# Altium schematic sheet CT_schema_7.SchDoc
size 522 x 483 mm
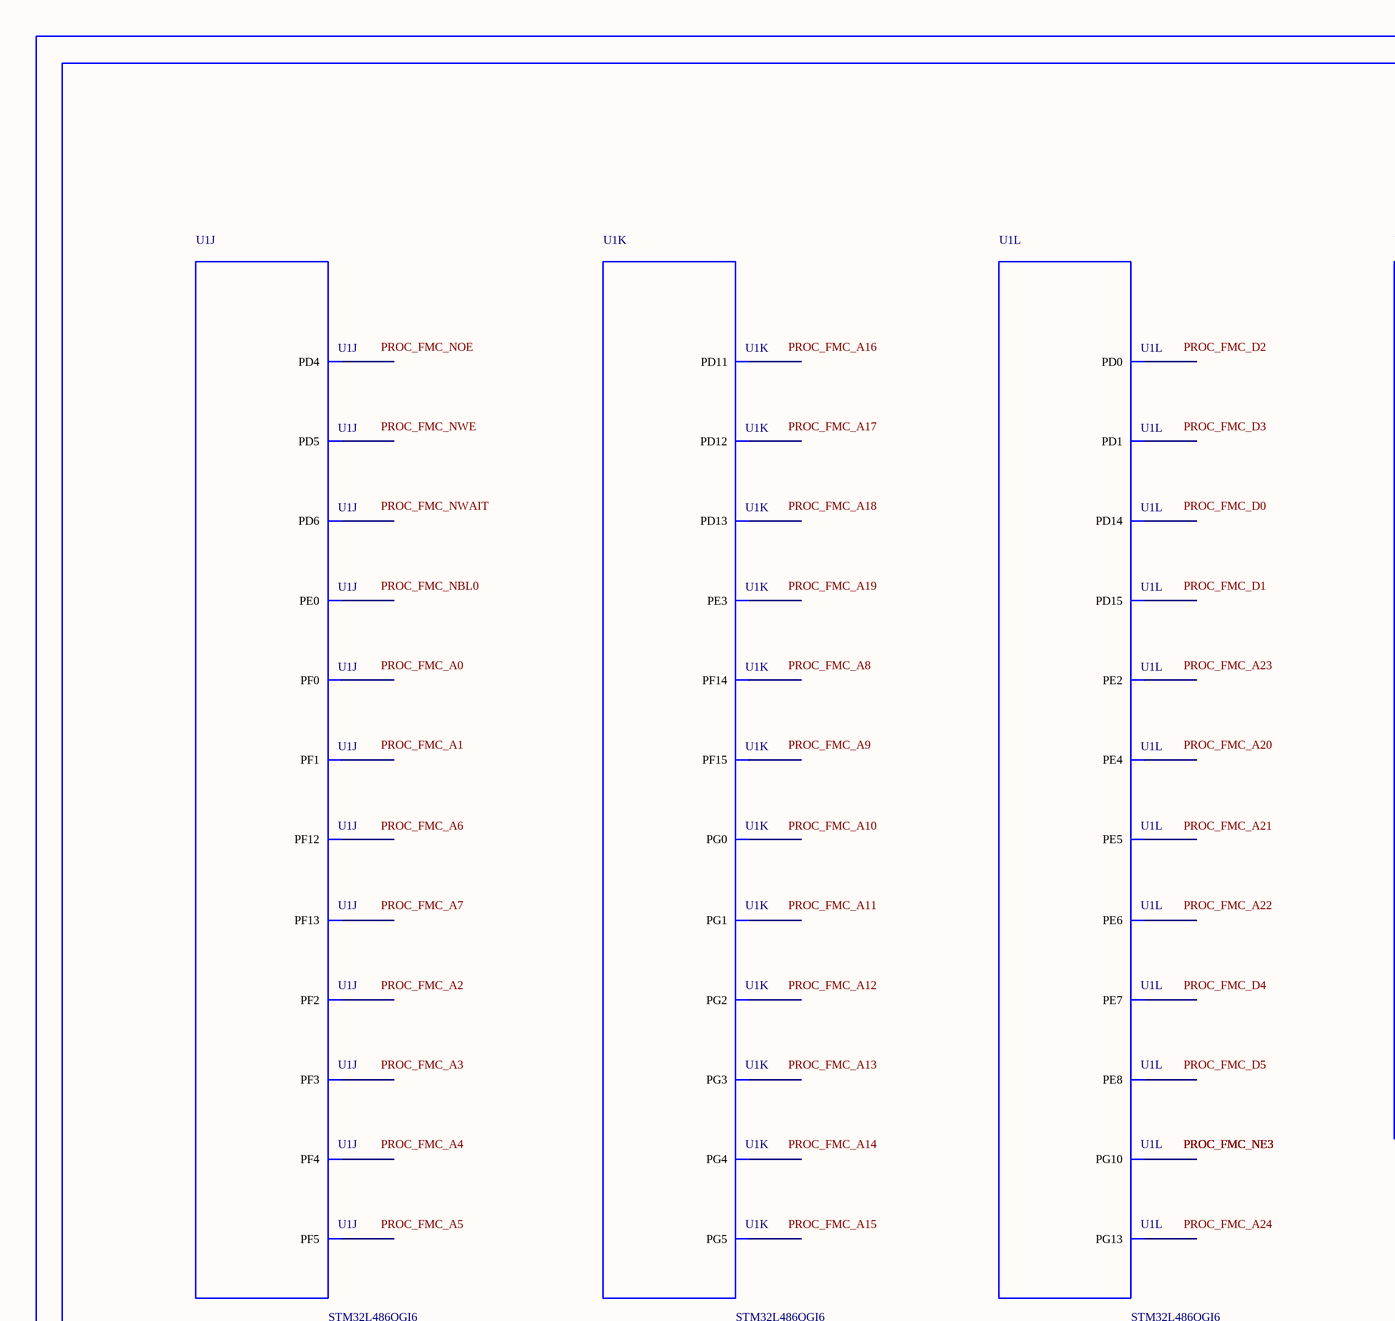
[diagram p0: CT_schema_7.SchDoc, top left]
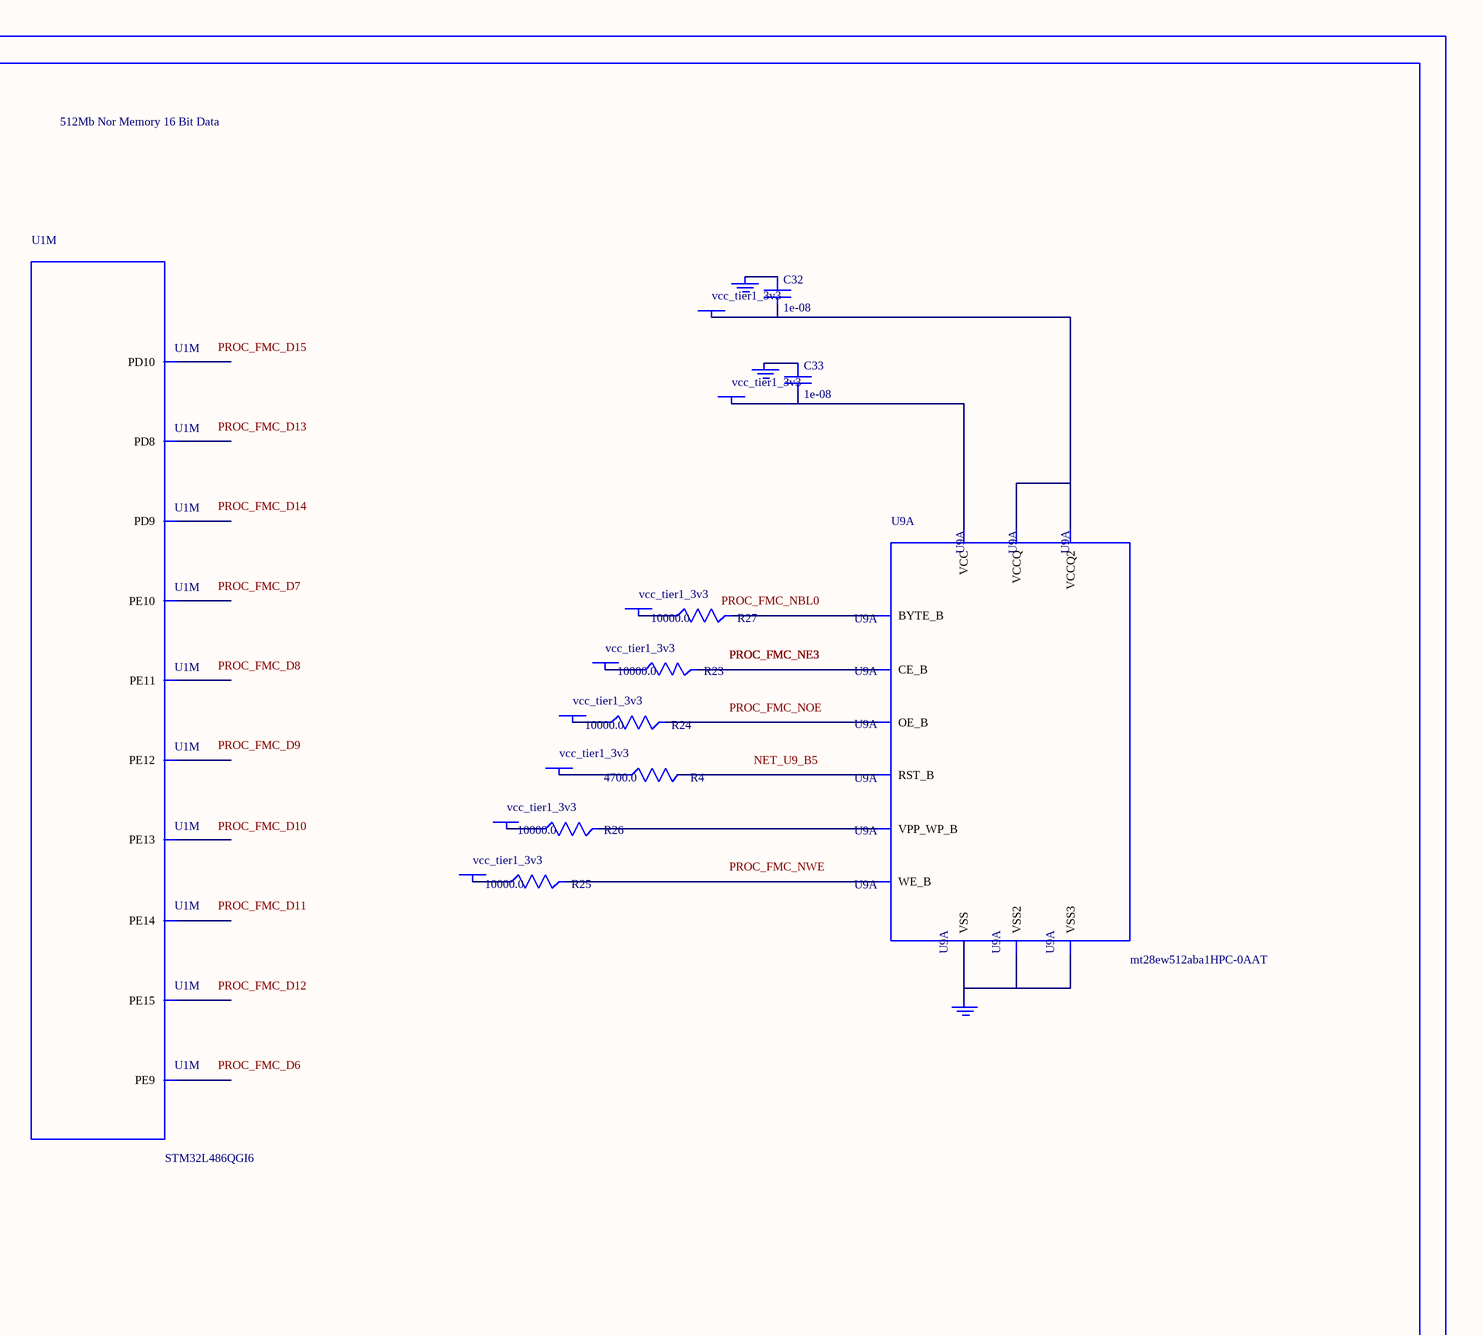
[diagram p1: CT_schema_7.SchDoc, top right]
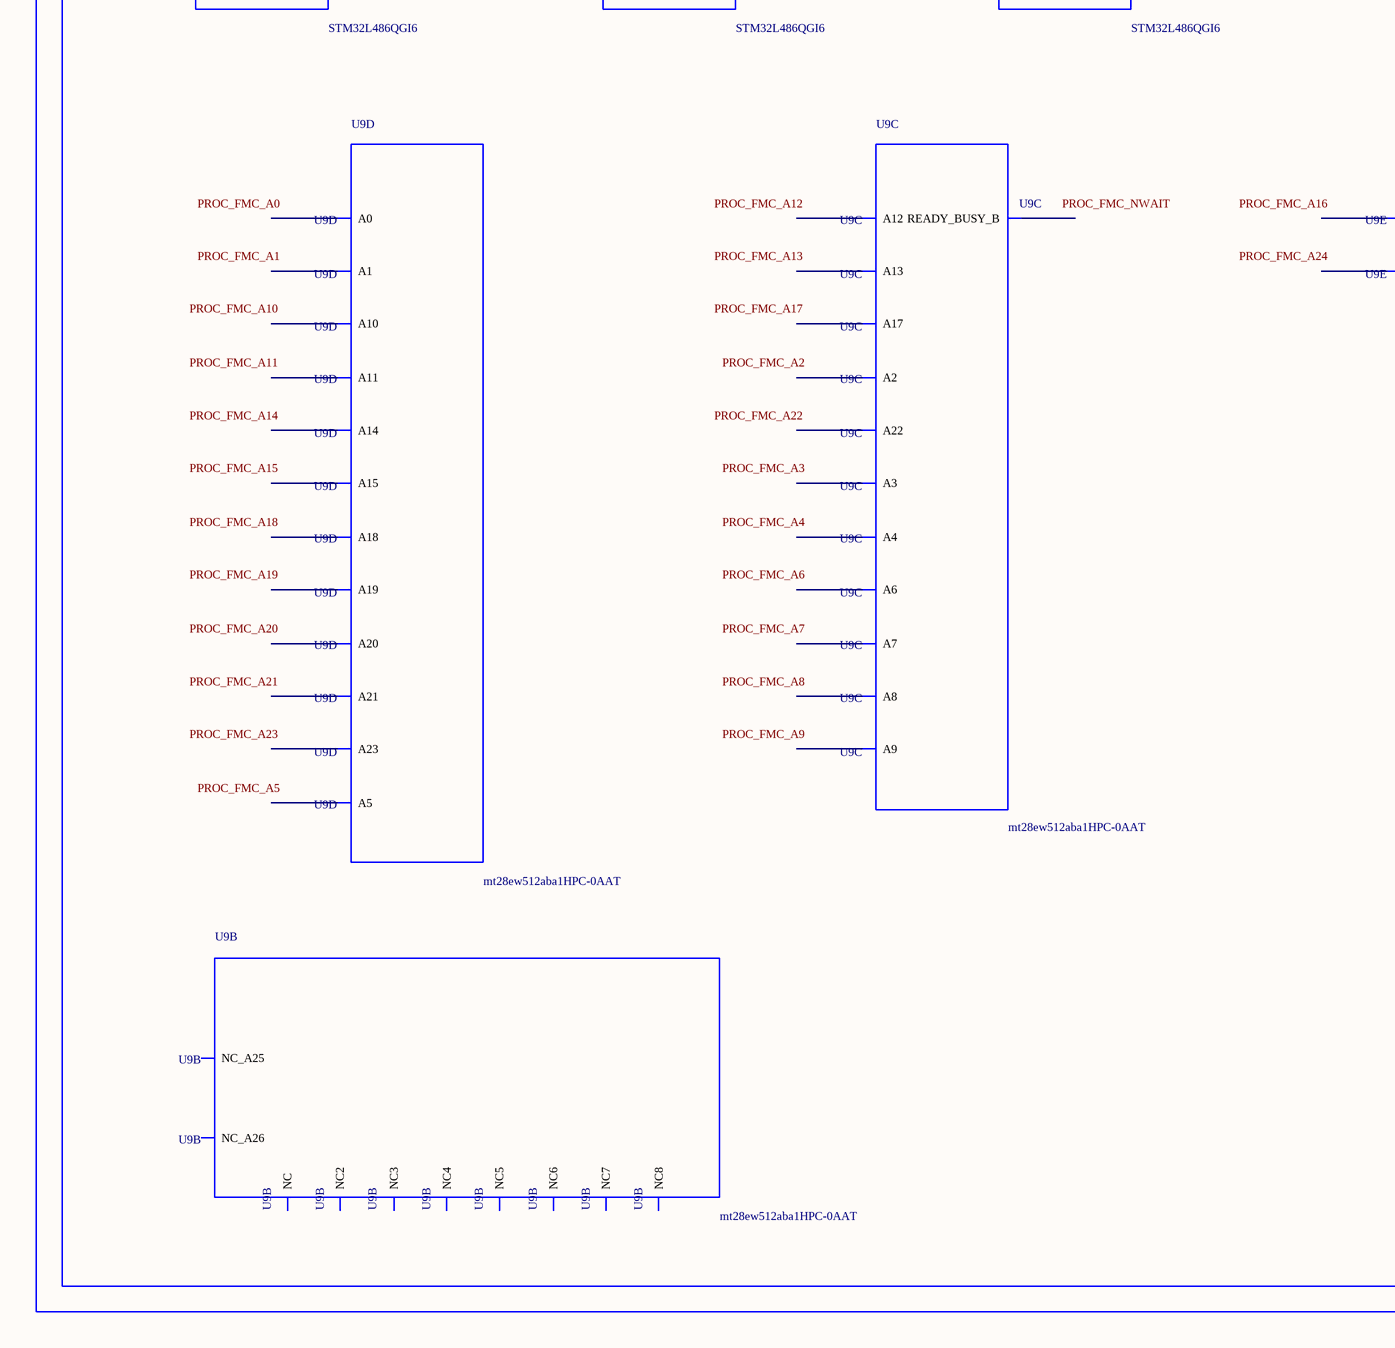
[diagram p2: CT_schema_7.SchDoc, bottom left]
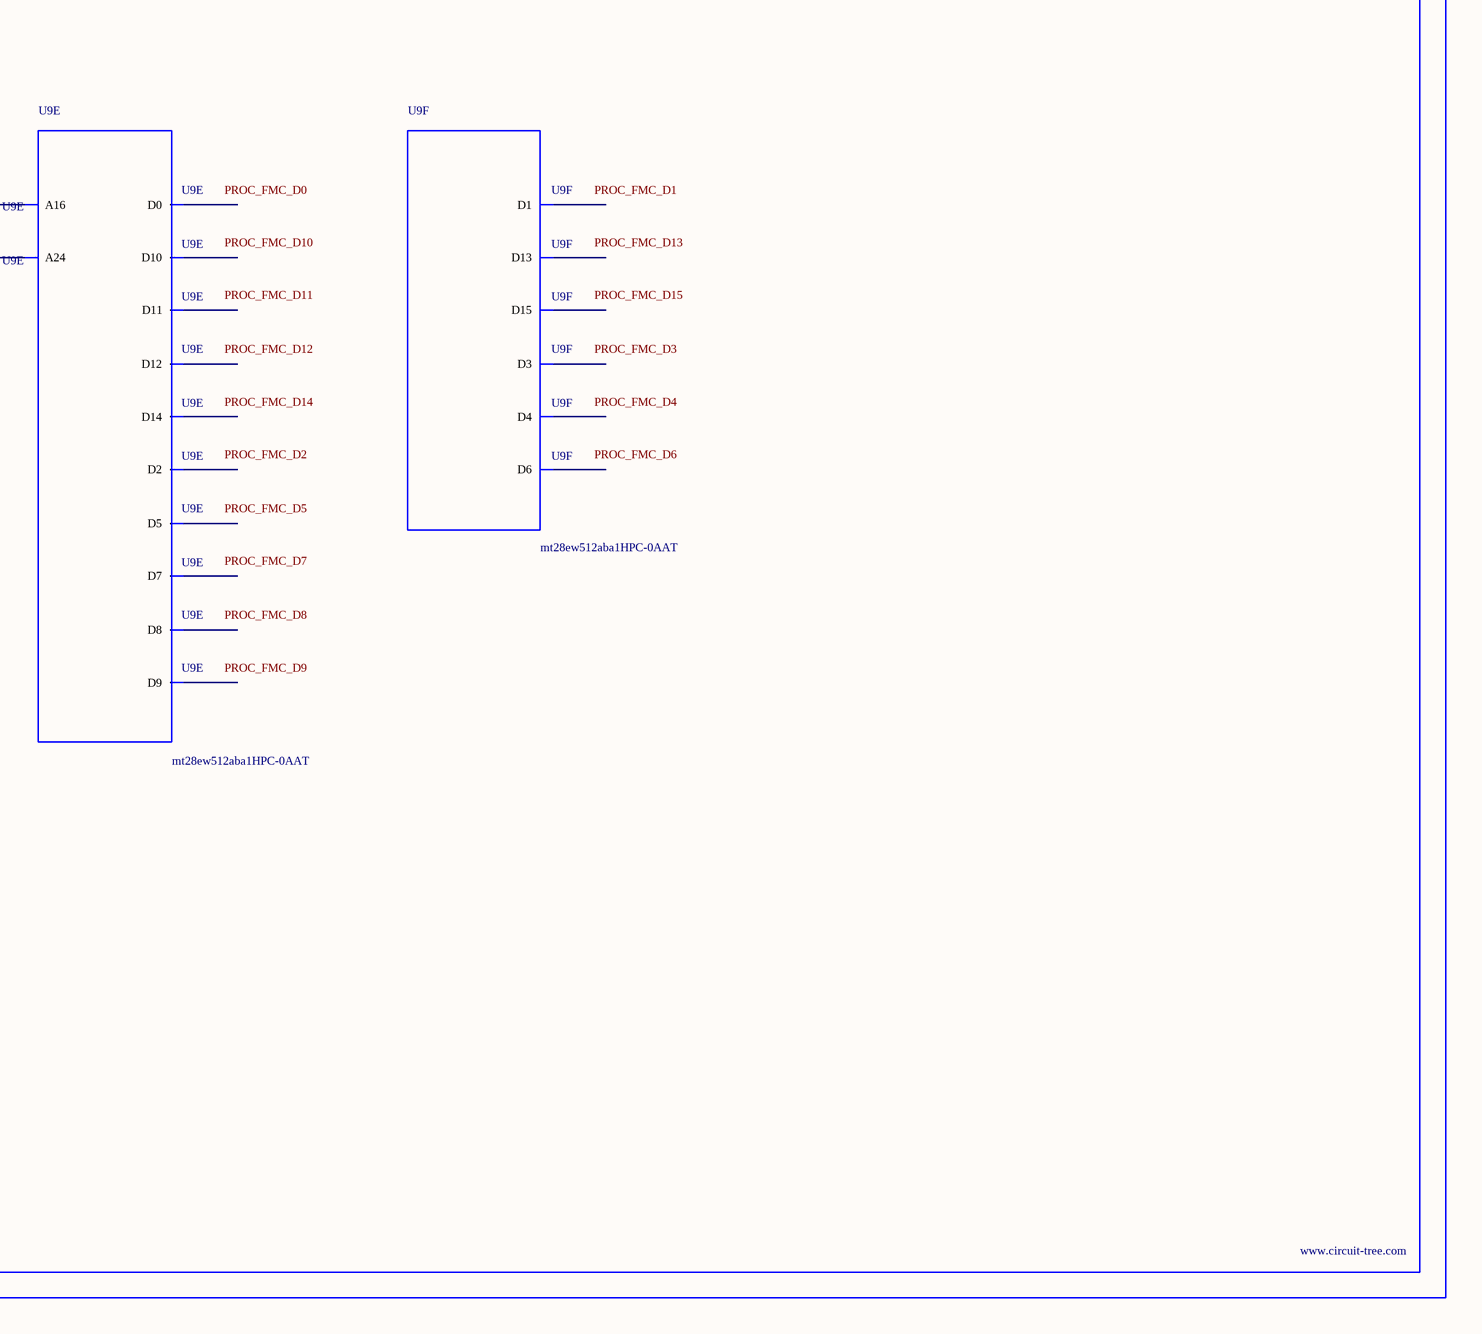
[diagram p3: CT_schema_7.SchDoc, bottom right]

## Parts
BORDER6  (no value)
C32  1e-08  [C0402]
C33  1e-08  [C0402]
GND_INSTANCE_6_0  (no value)
GND_INSTANCE_6_1  (no value)
GND_INSTANCE_6_2  (no value)
POWER_INSTANCE_6_0  vcc_tier1_3v3
POWER_INSTANCE_6_1  vcc_tier1_3v3
POWER_INSTANCE_6_2  vcc_tier1_3v3
POWER_INSTANCE_6_3  vcc_tier1_3v3
POWER_INSTANCE_6_4  vcc_tier1_3v3
POWER_INSTANCE_6_5  vcc_tier1_3v3
POWER_INSTANCE_6_6  vcc_tier1_3v3
POWER_INSTANCE_6_7  vcc_tier1_3v3
R4  4700.0  [R0603]
R23  10000.0  [R0603]
R24  10000.0  [R0603]
R25  10000.0  [R0603]
R26  10000.0  [R0603]
R27  10000.0  [R0603]
U1  STM32L486QGI6  [UFBGA132]  (parts J,K,L,M of 13)
U9  mt28ew512aba1HPC-0AAT  [LBGA-64]  (parts A,B,C,D,E,F of 6)

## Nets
NetC32_1: C32.1 GND_INSTANCE_6_0.0(GND)
NetC32_2: C32.2 POWER_INSTANCE_6_0.0(PWR) U9.D8(VCCQ) U9.F1(VCCQ2)
NetC33_1: C33.1 GND_INSTANCE_6_1.0(GND)
NetC33_2: C33.2 POWER_INSTANCE_6_1.0(PWR) U9.G5(VCC)
NetGND_INSTANCE_6_2_0: GND_INSTANCE_6_2.0(GND) U9.E8(VSS) U9.H2(VSS2) U9.H7(VSS3)
NetPOWER_INSTANCE_6_2_0: POWER_INSTANCE_6_2.0(PWR) R23.1
NetPOWER_INSTANCE_6_3_0: POWER_INSTANCE_6_3.0(PWR) R24.1
NetPOWER_INSTANCE_6_4_0: POWER_INSTANCE_6_4.0(PWR) R25.1
NetPOWER_INSTANCE_6_5_0: POWER_INSTANCE_6_5.0(PWR) R26.1
NetPOWER_INSTANCE_6_6_0: POWER_INSTANCE_6_6.0(PWR) R27.1
NetPOWER_INSTANCE_6_7_0: POWER_INSTANCE_6_7.0(PWR) R4.1
NetR4_2: R4.2 U9.B5(RST_B)
NetR23_2: R23.2 U9.F2(CE_B)
NetR24_2: R24.2 U9.G2(OE_B)
NetR25_2: R25.2 U9.A5(WE_B)
NetR26_2: R26.2 U9.B4(VPP_WP_B)
NetR27_2: R27.2 U9.F7(BYTE_B)

Not connected (* = marked no-connect by the designer): U1 A1(PE3) A6(PD5) B1(PE4) B2(PE2) B6(PD6) B7(PD4) B9(PD1) C2(PE5) C3(PE0) C7(PG13) C9(PD0) D2(PE6) D4(PF2) D5(PF1) D6(PF0) D8(PG10) E4(PF3) E9(PG5) F3(PF4) F4(PF5) F9(PG3) F10(PG4) G9(PG1) G10(PG2) H9(PG0) H10(PD15) H11(PD14) H12(PD13) J7(PF12) J8(PF14) J9(PF15) J10(PD12) J11(PD11) J12(PD10) K7(PF13) K8(PD9) K9(PD8) L7(PE8) L8(PE10) L9(PE12) M7(PE7) M8(PE9) M9(PE11) M10(PE13) M11(PE14) M12(PE15); U9 A1(NC) A2(A3) A3(A7) A4(READY_BUSY_B) A6(A9) A7(A13) A8(NC2) B1(NC_A26) B2(A4) B3(A17) B6(A8) B7(A12) B8(A22) C1(NC3) C2(A2) C3(A6) C4(A18) C5(A21) C6(A10) C7(A14) C8(A23) D1(NC4) D2(A1) D3(A5) D4(A20) D5(A19) D6(A11) D7(A15) E1(NC5) E2(A0) E3(D0) E4(D2) E5(D5) E6(D7) E7(A16) F3(D8) F4(D10) F5(D12) F6(D14) F8(A24) G1(NC6) G3(D9) G4(D11) G6(D13) G7(D15) G8(NC_A25) H1(NC7) H3(D1) H4(D3) H5(D4) H6(D6) H8(NC8)

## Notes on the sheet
- Labels drawn without touching a wire or pin: NET_U9_B5, PROC_FMC_A0, PROC_FMC_A1, PROC_FMC_A2, PROC_FMC_A3, PROC_FMC_A4, PROC_FMC_A5, PROC_FMC_A6, PROC_FMC_A7, PROC_FMC_A8, PROC_FMC_A9, PROC_FMC_A10, PROC_FMC_A11, PROC_FMC_A12, PROC_FMC_A13, PROC_FMC_A14, PROC_FMC_A15, PROC_FMC_A16, PROC_FMC_A17, PROC_FMC_A18, PROC_FMC_A19, PROC_FMC_A20, PROC_FMC_A21, PROC_FMC_A22, PROC_FMC_A23, PROC_FMC_A24, PROC_FMC_D0, PROC_FMC_D1, PROC_FMC_D2, PROC_FMC_D3, PROC_FMC_D4, PROC_FMC_D5, PROC_FMC_D6, PROC_FMC_D7, PROC_FMC_D8, PROC_FMC_D9, PROC_FMC_D10, PROC_FMC_D11, PROC_FMC_D12, PROC_FMC_D13, PROC_FMC_D14, PROC_FMC_D15, PROC_FMC_NBL0, PROC_FMC_NOE, PROC_FMC_NWAIT, PROC_FMC_NWE

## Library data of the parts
BORDER6 = BORDER_PAGE6
C32 C33 = C0402C103K3RAC
GND_INSTANCE_6_0-GND_INSTANCE_6_2 = GND
POWER_INSTANCE_6_0-POWER_INSTANCE_6_7 = PWR
R4 = RC0603JR-074K7L
R23-R27 = RC0603JR-0710KL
